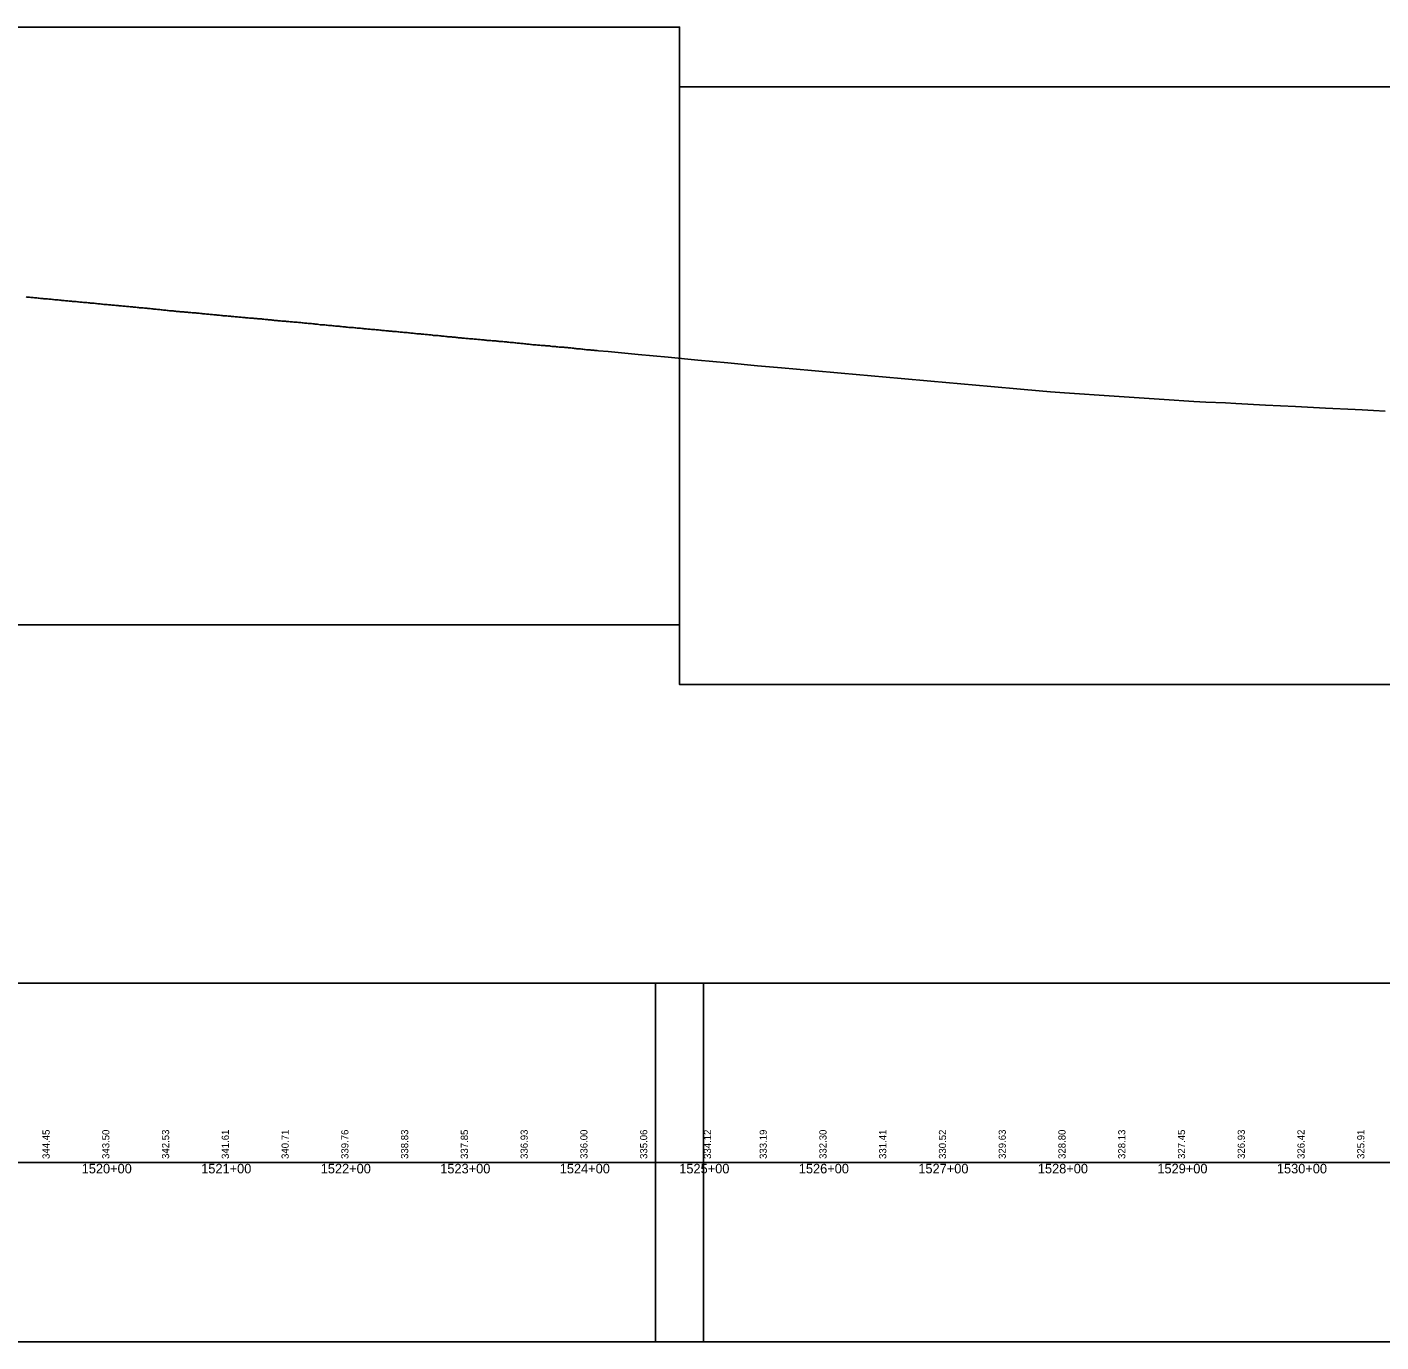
# Model space of a CAD drawing. Extents: x -3627 to 47473, y 2850 to 4350.
# Drawn here: x 39407 to 40540, y 2850 to 3950 of the extents above; entities that cross this region are included whole.
import ezdxf

# ---------------------------------------------------------------- set-up
doc = ezdxf.new("R2010")
doc.units = 0
for name, color, linetype in [('RD_DDB_Profile_EX', 7, 'Continuous'), ('RD_DDB_StaTX', 7, 'Continuous'), ('RD_DDB_StripGrade', 7, 'Continuous'), ('RD_GPK_Profile_Cell', 7, 'Continuous'), ('RD_SHT_ShtClip', 7, 'Continuous')]:
    doc.layers.add(name, color=color, linetype=linetype)

msp = doc.modelspace()

# ---------------------------------------------------------------- linework, layer by layer
at = {"layer": 'RD_DDB_Profile_EX'}
for points in [[(39406.589693, 3724.247515), (39407.584512, 3724.1469), (39408.587243, 3724.04711), (39409.59182, 3723.99644), (39410.584761, 3723.89668), (39411.589377, 3723.79615), (39412.592077, 3723.69654), (39413.586894, 3723.596065), (39414.589626, 3723.446435), (39415.584417, 3723.39558), (39416.58715, 3723.29635), (39417.591714, 3723.19566), (39418.584665, 3723.04589), (39419.589279, 3722.995155), (39420.582188, 3722.895615), (39421.586793, 3722.74536), (39422.589527, 3722.645715), (39423.582444, 3722.59571), (39424.587049, 3722.544735), (39425.580003, 3722.444985), (39426.584562, 3722.294945), (39427.587306, 3722.24531), (39428.582136, 3722.144405), (39429.584819, 3722.04504), (39430.58943, 3721.94454), (39431.582392, 3721.795025), (39432.586941, 3721.74427), (39433.579906, 3721.694495), (39434.584522, 3721.643695), (39435.587198, 3721.44493), (39436.582034, 3721.344355), (39437.584766, 3721.244395), (39438.579557, 3721.19378), (39439.58229, 3721.093205), (39440.586892, 3720.993665), (39441.579801, 3720.94388), (39442.584415, 3720.79375), (39443.57739, 3720.793285), (39444.581924, 3720.69315), (39445.584658, 3720.5435), (39446.57952, 3720.442895), (39447.582181, 3720.39324), (39448.575158, 3720.293455), (39449.579762, 3720.14336), (39450.582437, 3720.044035), (39451.577286, 3719.993115), (39452.580017, 3719.893445), (39453.584543, 3719.743), (39454.577542, 3719.6432), (39455.582065, 3719.592755), (39456.575052, 3719.54296), (39457.577798, 3719.443285), (39458.582322, 3719.34284), (39459.575308, 3719.243045), (39460.579924, 3719.142185), (39461.582578, 3719.042535), (39462.577432, 3718.94236), (39463.58018, 3718.892275), (39464.582835, 3718.793015), (39465.577688, 3718.692445), (39466.580357, 3718.592765), (39467.575211, 3718.491765), (39468.577944, 3718.4417), (39469.582473, 3718.29164), (39470.575467, 3718.142285), (39471.5782, 3718.042615), (39472.58273, 3717.9426), (39473.575723, 3717.941945), (39474.580322, 3717.79193), (39475.573247, 3717.692125)], [(39475.573247, 3717.692125), (39476.577845, 3717.591225), (39477.580578, 3717.492015), (39478.573503, 3717.29351), (39479.578101, 3717.29177), (39480.580748, 3717.24166), (39481.575624, 3717.141525), (39482.578357, 3717.091405), (39483.573129, 3716.99032), (39484.57588, 3716.89068), (39485.578613, 3716.791495), (39486.573385, 3716.690415), (39487.576136, 3716.640775), (39488.580732, 3716.54077), (39489.573641, 3716.44051), (39490.576393, 3716.341325), (39491.57126, 3716.241215), (39492.573898, 3716.141075), (39493.578493, 3715.991105), (39494.57142, 3715.940815), (39495.576015, 3715.840355), (39496.578749, 3715.74119), (39497.571677, 3715.641865), (39498.576271, 3715.54145), (39499.579006, 3715.441275), (39500.573793, 3715.390185), (39501.576528, 3715.24103), (39502.571399, 3715.23994), (39503.57405, 3715.140275), (39504.576784, 3715.04112), (39505.571655, 3714.94108), (39506.574306, 3714.840875), (39507.578899, 3714.740435), (39508.571809, 3714.640115), (39509.57642, 3714.5391), (39510.569435, 3714.43986), (39511.572066, 3714.390205), (39512.576677, 3714.239195), (39513.569691, 3714.14048), (39514.574178, 3714.03949), (39515.576934, 3713.89036), (39516.57181, 3713.8398), (39517.574435, 3713.740125), (39518.567471, 3713.59032), (39519.571956, 3713.48988), (39520.574692, 3713.389665), (39521.56959, 3713.28964), (39522.572213, 3713.14108), (39523.576801, 3713.090115), (39524.569846, 3712.990295), (39525.57247, 3712.891155), (39526.567347, 3712.740655), (39527.570102, 3712.640375), (39528.574579, 3712.589965), (39529.567603, 3712.490155), (39530.570337, 3712.439905), (39531.574836, 3712.339455), (39532.56786, 3712.14081), (39533.570484, 3712.0411), (39534.575093, 3711.990705), (39535.568116, 3711.891455), (39536.570761, 3711.84117), (39537.565639, 3711.788915), (39538.568372, 3711.640395), (39539.571018, 3711.540695), (39540.565895, 3711.490165), (39541.568649, 3711.439905), (39542.571275, 3711.340775), (39543.566151, 3711.240245), (39544.568796, 3711.1411), (39545.571532, 3710.990855), (39546.566408, 3710.890325), (39547.569053, 3710.890075), (39548.56207, 3710.839735), (39549.566685, 3710.68983), (39550.56931, 3710.639065), (39551.562326, 3710.53929), (39552.566831, 3710.389915), (39553.569567, 3710.24133), (39554.562582, 3710.190445), (39555.567088, 3710.04111), (39556.569824, 3709.98657), (39557.562858, 3709.890525), (39558.567345, 3709.790635), (39559.570081, 3709.69095), (39560.563011, 3709.59113), (39561.567602, 3709.49017), (39562.560638, 3709.439295), (39563.563268, 3709.290695), (39564.566003, 3709.191025), (39565.560894, 3709.14045), (39566.563525, 3709.04078), (39567.56626, 3708.990615), (39568.561046, 3708.889485), (39569.563781, 3708.790865), (39570.566535, 3708.642165), (39571.561303, 3708.542185), (39572.564038, 3708.39246), (39573.557063, 3708.341635), (39574.56156, 3708.290705), (39575.564314, 3708.192025)], [(39575.564314, 3708.192025), (39576.557319, 3708.14123), (39577.561816, 3708.0413), (39578.56457, 3707.991605), (39579.55748, 3707.94083), (39580.562073, 3707.740875), (39581.564827, 3707.691195), (39582.557737, 3707.64092), (39583.562349, 3707.490955), (39584.555355, 3707.391155), (39585.557993, 3707.34101), (39586.562606, 3707.24054), (39587.555515, 3707.14124), (39588.55825, 3707.0911), (39589.562862, 3706.99063), (39590.555772, 3706.891325), (39591.558524, 3706.79072), (39592.563119, 3706.74072), (39593.556028, 3706.591885), (39594.55878, 3706.49173), (39595.55355, 3706.391165), (39596.556303, 3706.341015), (39597.559037, 3706.29091), (39598.553807, 3706.18979), (39599.556559, 3706.090635), (39600.559293, 3705.991005), (39601.552202, 3705.941225), (39602.556816, 3705.89073), (39603.55955, 3705.790655), (39604.552475, 3705.641315), (39605.557072, 3705.540825), (39606.549981, 3705.44105), (39607.552731, 3705.34141), (39608.557328, 3705.241375), (39609.550254, 3705.191135), (39610.552988, 3705.04193), (39611.557585, 3704.941915), (39612.55051, 3704.84167), (39613.553244, 3704.7916), (39614.555898, 3704.642365), (39615.550767, 3704.54176), (39616.5535, 3704.49211), (39617.55617, 3704.34245), (39618.549157, 3704.292665), (39619.553756, 3704.1922), (39620.556413, 3704.092545), (39621.549413, 3704.042375), (39622.554013, 3703.991885), (39623.546921, 3703.8425), (39624.549669, 3703.792845), (39625.552401, 3703.74248), (39626.547178, 3703.641815), (39627.549925, 3703.492565), (39628.552588, 3703.44293), (39629.547434, 3703.3423), (39630.550181, 3703.24266), (39631.552845, 3703.142675), (39632.545822, 3703.04325), (39633.550437, 3702.992755), (39634.553102, 3702.892775), (39635.546078, 3702.84268), (39636.548822, 3702.74339), (39637.553359, 3702.692535), (39638.546334, 3702.54311), (39639.549078, 3702.39349), (39640.553616, 3702.342975), (39641.54659, 3702.243535), (39642.549274, 3702.1442), (39643.542242, 3702.093825), (39644.546846, 3701.99331), (39645.54952, 3701.893395), (39646.542498, 3701.79364), (39647.54523, 3701.69404), (39648.549777, 3701.5935), (39649.542754, 3701.444595), (39650.545486, 3701.34521), (39651.550034, 3701.194475), (39652.54301, 3700.995245), (39653.609013, 3700.93959), (39654.597114, 3700.940315), (39655.586777, 3700.889625), (39656.575838, 3700.79139), (39657.566426, 3700.693), (39658.549043, 3700.59428), (39659.543847, 3700.445245), (39660.536924, 3700.34657), (39661.521137, 3700.2972), (39662.51304, 3700.24741), (39663.49762, 3700.049505), (39664.494419, 3700), (39665.54485, 3699.896015), (39666.539673, 3699.84515), (39667.542413, 3699.795315), (39668.545106, 3699.695915), (39669.539929, 3699.5457), (39670.54262, 3699.44605), (39671.545363, 3699.246585), (39672.538308, 3699.19625), (39673.542877, 3699.145935), (39674.545619, 3699.046485), (39675.538563, 3698.846875)], [(39675.538563, 3698.846875), (39676.541264, 3698.797205), (39677.545876, 3698.796395), (39678.538819, 3698.59679), (39679.541521, 3698.59699), (39680.546133, 3698.546315), (39681.539075, 3698.446715), (39682.541777, 3698.34723), (39683.536599, 3698.19662), (39684.539299, 3698.14697), (39685.542034, 3698.09718), (39686.536855, 3697.996365), (39687.539556, 3697.89675), (39688.544161, 3697.79641), (39689.537111, 3697.6468), (39690.539812, 3697.597), (39691.534628, 3697.496545), (39692.53736, 3697.39657), (39693.541939, 3697.396045), (39694.534884, 3697.246635), (39695.537616, 3697.096985), (39696.542196, 3697.09633), (39697.53514, 3696.896555), (39698.53971, 3696.895665), (39699.542453, 3696.846245), (39700.535396, 3696.74665), (39701.539967, 3696.645965), (39702.53292, 3696.545835), (39703.537528, 3696.49547), (39704.540224, 3696.097), (39705.533176, 3696.096825), (39706.537784, 3696.145775), (39707.540481, 3695.99653), (39708.533432, 3695.896395), (39709.538002, 3695.74627), (39710.530956, 3695.69574), (39711.535564, 3695.64538), (39712.538266, 3695.546165), (39713.531212, 3695.44639), (39714.53582, 3695.34569), (39715.538523, 3695.29607), (39716.533344, 3695.195405), (39717.536044, 3695.095985), (39718.528992, 3694.99621), (39719.533608, 3694.895715), (39720.536301, 3694.745495), (39721.531123, 3694.64499), (39722.533822, 3694.59581), (39723.536558, 3694.495795), (39724.531388, 3694.445315), (39725.534079, 3694.345905), (39726.536822, 3694.196455), (39727.529766, 3694.14544), (39728.534336, 3694.046), (39729.52729, 3693.94641), (39730.529988, 3693.84659), (39731.5346, 3693.74609), (39732.527546, 3693.646315), (39733.530251, 3693.497015), (39734.532985, 3693.39705), (39735.527767, 3693.39605), (39736.530507, 3693.296935), (39737.533242, 3693.197145), (39738.52803, 3693.14633), (39739.530764, 3693.046715), (39740.523679, 3692.94695), (39741.526412, 3692.847335), (39742.53102, 3692.746665), (39743.523935, 3692.64691), (39744.526668, 3692.597315), (39745.531282, 3692.496765), (39746.524191, 3692.29742), (39747.526925, 3691.998005), (39748.529642, 3691.99812), (39749.524448, 3692.09712), (39750.527185, 3691.997745), (39751.520094, 3691.848075), (39752.524709, 3691.747475), (39753.52742, 3691.59784), (39754.52035, 3691.54797), (39755.523085, 3691.498355), (39756.527677, 3691.297215), (39757.520609, 3691.147885), (39758.523341, 3691.098235), (39759.527938, 3690.997835), (39760.520865, 3690.99808), (39761.523584, 3690.94842), (39762.518389, 3690.79778), (39763.521121, 3690.69827), (39764.525716, 3690.59764), (39765.518645, 3690.44798), (39766.523237, 3690.347455), (39767.516169, 3690.247805), (39768.52078, 3690.097305), (39769.523494, 3690.04756), (39770.518303, 3689.996885), (39771.521015, 3689.84714), (39772.515826, 3689.7466), (39773.518565, 3689.646985), (39774.523141, 3689.59646), (39775.516083, 3689.446855)], [(39775.516083, 3689.446855), (39776.520698, 3689.346175), (39777.523398, 3689.246725), (39778.518221, 3689.19589), (39779.520919, 3689.146095), (39780.515744, 3689.09539), (39781.518477, 3688.995605), (39782.523042, 3688.89525), (39783.516, 3688.7957), (39784.520562, 3688.74495), (39785.513524, 3688.644975), (39786.51813, 3688.54465), (39787.520827, 3688.395725), (39788.515652, 3688.29512), (39789.518339, 3688.244995), (39790.513175, 3688.19378), (39791.515909, 3688.044705), (39792.520468, 3687.89446), (39793.513432, 3687.844685), (39794.518046, 3687.843895), (39795.520726, 3687.744555), (39796.515557, 3687.643615), (39797.518246, 3687.54428), (39798.513079, 3687.49333), (39799.515825, 3687.39371), (39800.520363, 3687.29319), (39801.513336, 3687.24155), (39802.517883, 3687.093245), (39803.510858, 3687.04314), (39804.515471, 3686.94262), (39805.51814, 3686.843005), (39806.51298, 3686.74234), (39807.515728, 3686.69272), (39808.518397, 3686.543435), (39809.511371, 3686.44366), (39810.515971, 3686.342825), (39811.518655, 3686.24353), (39812.511628, 3686.193755), (39813.516228, 3686.14259), (39814.509138, 3685.993485), (39815.511884, 3685.844155), (39816.514618, 3685.79422), (39817.509394, 3685.69326), (39818.512129, 3685.59274), (39819.514875, 3685.543175), (39820.509651, 3685.34431), (39821.512386, 3685.294045), (39822.515121, 3685.194695), (39823.50804, 3685.0949), (39824.512643, 3685.04414), (39825.515377, 3684.84506), (39826.508287, 3684.74526), (39827.511031, 3684.645585), (39828.515634, 3684.545145), (39829.508544, 3684.445345), (39830.511279, 3684.295915), (39831.515891, 3684.24523), (39832.5088, 3684.195175), (39833.511535, 3684.14529), (39834.51427, 3683.99566), (39835.509057, 3683.94502), (39836.511792, 3683.845385), (39837.504745, 3683.74583), (39838.507436, 3683.69618), (39839.512048, 3683.64571), (39840.505, 3683.54592), (39841.507693, 3683.396465), (39842.512297, 3683.3458), (39843.505256, 3683.2458), (39844.50795, 3683.19598), (39845.510684, 3683.09654), (39846.505504, 3682.896515), (39847.508206, 3682.84645), (39848.510941, 3682.74697), (39849.50576, 3682.646595), (39850.508456, 3682.596545), (39851.511198, 3682.447055), (39852.504137, 3682.34726), (39853.508713, 3682.24681), (39854.511449, 3682.246825), (39855.504393, 3682.196755), (39856.507099, 3682.097285), (39857.511705, 3681.847075), (39858.504643, 3681.847005), (39859.507356, 3681.797385), (39860.511962, 3681.64612), (39861.504899, 3681.59655), (39862.507608, 3681.54737), (39863.500543, 3681.497395), (39864.505155, 3681.347205), (39865.507865, 3681.197705), (39866.500799, 3681.097925), (39867.505411, 3680.947305), (39868.508121, 3680.89769), (39869.501051, 3680.797925), (39870.503786, 3680.69831), (39871.508378, 3680.59779), (39872.501307, 3680.44812), (39873.504039, 3680.34841), (39874.506762, 3680.248795), (39875.501563, 3680.098215)], [(39875.501563, 3680.098215), (39876.504295, 3680.09851), (39877.507016, 3679.998895), (39878.501819, 3679.84831), (39879.504551, 3679.74861), (39880.507273, 3679.698995), (39881.50019, 3679.59923), (39882.504807, 3679.49871), (39883.50753, 3679.39914), (39884.499807, 3679.299425), (39885.50513, 3679.249535), (39893.742492, 3678.473185), (39918.757386, 3676.115585), (39943.772234, 3673.75801), (39968.787035, 3671.40045), (39993.801789, 3669.042905), (40018.704259, 3666.69592), (40038.715335, 3664.914875), (40063.709321, 3662.69058), (40088.703307, 3660.466405), (40113.724138, 3658.24012), (40138.713421, 3656.01718), (40163.702675, 3653.7941), (40188.6919, 3651.57087), (40213.681097, 3649.3475), (40238.670264, 3647.12398), (40254.345299, 3645.72915), (40263.664825, 3644.899915), (40275.478941, 3644.107225), (40283.664939, 3643.557895), (40308.672553, 3641.879865), (40333.679512, 3640.202025), (40358.686438, 3638.52434), (40383.652391, 3636.849225), (40393.670577, 3636.34028), (40410.105314, 3635.505915), (40418.663018, 3635.071295), (40443.685743, 3633.801055), (40468.689097, 3632.532595), (40493.703814, 3631.26479), (40518.68488, 3629.99879), (40524.397971, 3629.70902), (40533.93499, 3629.224785), (40543.684365, 3628.73042)]]:
    msp.add_lwpolyline(points, dxfattribs=at)
at = {"layer": 'RD_GPK_Profile_Cell'}
msp.add_line((1000, 3000), (46705.077602, 3000), dxfattribs=at)
at = {"layer": 'RD_SHT_ShtClip'}
for points in [[(38453.33, 3950), (38453.33, 3450), (39953.33, 3450), (39953.33, 3450), (39953.33, 3950), (39953.33, 3950)], [(39953.33, 3900), (39953.33, 3400), (41453.33, 3400), (41453.33, 3400), (41453.33, 3900), (41453.33, 3900)], [(38433.33, 3150), (39973.33, 3150), (39973.33, 2850), (38433.33, 2850)], [(39933.33, 3150), (41473.33, 3150), (41473.33, 2850), (39933.33, 2850)]]:
    msp.add_lwpolyline(points, close=True, dxfattribs=at)

# ---------------------------------------------------------------- texts
at = {"layer": 'RD_DDB_StaTX'}
for s, p in [('1520+00', (39453.125471, 2991)), ('1521+00', (39553.125471, 2991)), ('1522+00', (39653.125471, 2991)), ('1523+00', (39753.125471, 2991)), ('1524+00', (39853.125471, 2991)), ('1525+00', (39953.125471, 2991)), ('1526+00', (40053.125471, 2991)), ('1527+00', (40153.125471, 2991)), ('1528+00', (40253.125471, 2991)), ('1529+00', (40353.125471, 2991)), ('1530+00', (40453.125471, 2991))]:
    msp.add_text(s, height=8, dxfattribs=at).set_placement(p)
at = {"layer": 'RD_DDB_StripGrade'}
for s, p in [('344.45', (39426.33, 3003.073688)), ('343.50', (39476.33, 3003.073688)), ('342.53', (39526.33, 3003.073688)), ('341.61', (39576.33, 3003.073688)), ('340.71', (39626.33, 3003.073688)), ('339.76', (39676.33, 3003.073688)), ('338.83', (39726.33, 3003.073688)), ('337.85', (39776.33, 3003.073688)), ('336.93', (39826.33, 3003.073688)), ('336.00', (39876.33, 3003.073688)), ('335.06', (39926.33, 3003.073688)), ('334.12', (39979.733208, 3003.073688)), ('333.19', (40026.33, 3003.073688)), ('332.30', (40076.33, 3003.073688)), ('331.41', (40126.33, 3003.073688)), ('330.52', (40176.33, 3003.073688)), ('329.63', (40226.33, 3003.073688)), ('328.80', (40276.33, 3003.073688)), ('328.13', (40326.33, 3003.073688)), ('327.45', (40376.33, 3003.073688)), ('326.93', (40426.33, 3003.073688)), ('326.42', (40476.33, 3003.073688)), ('325.91', (40526.33, 3003.073688))]:
    msp.add_text(s, height=6, rotation=90, dxfattribs=at).set_placement(p)

doc.saveas('drawing.dxf')
